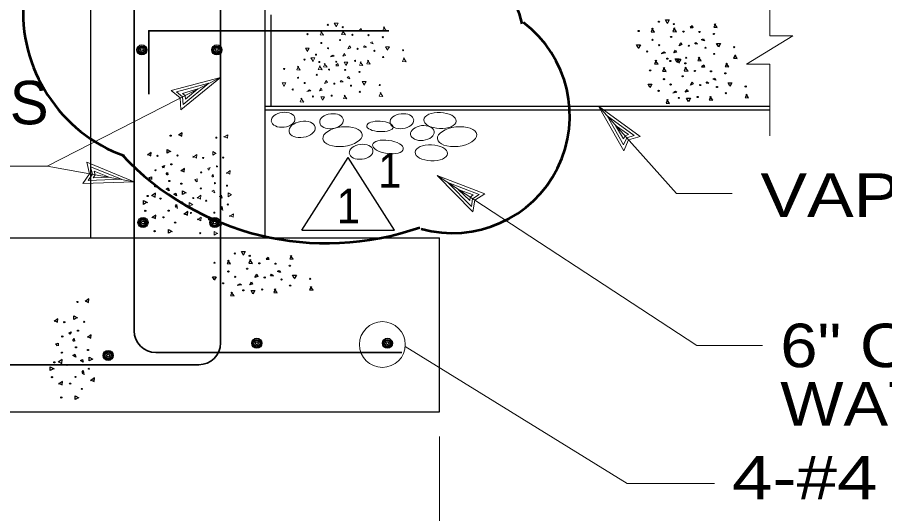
# Model space of a CAD drawing. Extents: x -28.1 to 13.9, y -16.1 to 13.9.
# Drawn here: x -22.908 to -20.417, y 1.852 to 3.278 of the extents above; entities that cross this region are included whole.
import ezdxf
from ezdxf.enums import TextEntityAlignment as Align

# ---------------------------------------------------------------- set-up
doc = ezdxf.new("R2010")
doc.units = 0
doc.header["$LTSCALE"] = 0.05
doc.layers.add('1', color=7, linetype='Continuous', lineweight=13)
doc.layers.add('2', color=7, linetype='Continuous', lineweight=13)

msp = doc.modelspace()

# ---------------------------------------------------------------- linework, layer by layer
at = {"layer": '1', "lineweight": 25}
for p, q in [((-22.19704, 2.64469), (-22.19704, 10.70469)), ((-22.69704, 2.64269), (-22.69704, 10.64469)), ((-22.17904, 3.02269), (-22.17904, 3.28569)), ((-22.19704, 3.02269), (-20.74704, 3.02269)), ((-22.19704, 3.01269), (-20.74704, 3.01269)), ((-22.09105, 2.66671), (-21.95805, 2.87571)), ((-21.82505, 2.66671), (-21.95805, 2.87571)), ((-22.09105, 2.66671), (-21.82505, 2.66671)), ((-23.19604, 2.64469), (-21.69604, 2.64469)), ((-21.69604, 2.14469), (-21.69604, 2.64469)), ((-23.19604, 2.14469), (-21.69604, 2.14469))]:
    msp.add_line(p, q, dxfattribs=at)
at = {"layer": '1', "lineweight": 35}
for p, q in [((-22.57304, 2.37769), (-22.57304, 4.38569)), ((-22.32504, 2.34269), (-22.32504, 4.38569)), ((-22.53082, 3.23983), (-21.84179, 3.23983)), ((-22.51004, 2.31469), (-21.80404, 2.31469)), ((-23.08904, 2.27969), (-22.38704, 2.27969))]:
    msp.add_line(p, q, dxfattribs=at)
at = {"layer": '1'}
for p, q in [((-20.74704, 3.22469), (-20.74704, 3.33369)), ((-20.81404, 3.14369), (-20.68104, 3.22469)), ((-20.74704, 3.22469), (-20.68104, 3.22469)), ((-20.81404, 3.14369), (-20.74704, 3.14369)), ((-20.74704, 2.93769), (-20.74704, 3.14369)), ((-22.32504, 3.10569), (-22.46704, 3.06769)), ((-22.32504, 3.10569), (-22.43904, 3.01269)), ((-22.35804, 3.08869), (-22.45104, 3.06369)), ((-22.39004, 3.07269), (-22.43404, 3.05969)), ((-22.35804, 3.08869), (-22.43204, 3.02769)), ((-22.39004, 3.07269), (-22.42504, 3.04269)), ((-22.43404, 3.04969), (-22.45104, 3.06369)), ((-22.42604, 3.05369), (-22.43404, 3.05969)), ((-22.43204, 3.02769), (-22.43404, 3.04969)), ((-22.42504, 3.04269), (-22.42604, 3.05369)), ((-21.23904, 3.02269), (-21.12004, 2.93569)), ((-21.23904, 3.02269), (-21.16604, 2.89469)), ((-21.21404, 2.99469), (-21.13704, 2.93869)), ((-21.21404, 2.99469), (-21.16704, 2.91169)), ((-21.19004, 2.96769), (-21.16704, 2.92869)), ((-21.19004, 2.96769), (-21.15304, 2.94169)), ((-21.15304, 2.94169), (-21.16304, 2.93769)), ((-21.16304, 2.93769), (-21.16704, 2.92869)), ((-21.15804, 2.93169), (-21.16704, 2.91169)), ((-21.13704, 2.93869), (-21.15804, 2.93169)), ((-22.82304, 2.85069), (-22.57304, 2.80569)), ((-22.57304, 2.80569), (-22.70904, 2.86169)), ((-22.60904, 2.81269), (-22.69804, 2.84869)), ((-22.69304, 2.82769), (-22.69804, 2.84869)), ((-22.70504, 2.80969), (-22.69304, 2.82769)), ((-22.69104, 2.81669), (-22.68504, 2.82569)), ((-22.64504, 2.81869), (-22.69104, 2.81669)), ((-22.64504, 2.81869), (-22.68804, 2.83569)), ((-22.68504, 2.82569), (-22.68804, 2.83569)), ((-21.70304, 2.82369), (-21.56604, 2.77069)), ((-21.70304, 2.82369), (-21.60004, 2.71869)), ((-22.57304, 2.80569), (-22.72004, 2.80069)), ((-22.60904, 2.81269), (-22.70504, 2.80969)), ((-21.67204, 2.80369), (-21.58204, 2.76869)), ((-21.67204, 2.80369), (-21.60404, 2.73469)), ((-21.64204, 2.78369), (-21.60904, 2.75169)), ((-21.64204, 2.78369), (-21.59904, 2.76769)), ((-21.59904, 2.76769), (-21.60804, 2.76169)), ((-21.58204, 2.76869), (-21.60104, 2.75669)), ((-21.60804, 2.76169), (-21.60904, 2.75169)), ((-21.60104, 2.75669), (-21.60404, 2.73469)), ((-21.69604, 2.07369), (-21.69604, 1.48469))]:
    msp.add_line(p, q, dxfattribs=at)
at = {"layer": '1', "lineweight": 35}
msp.add_lwpolyline([(-22.53082, 3.05783), (-22.53082, 3.23983), (-22.51533, 3.23983)], dxfattribs=at)
at = {"layer": '1'}
for points in [[(-22.94304, 2.85069), (-22.82304, 2.85069), (-22.32504, 3.10569)], [(-22.43904, 3.01269), (-22.44104, 3.04669), (-22.46704, 3.06769)], [(-21.23904, 3.02269), (-21.01504, 2.77169), (-20.85504, 2.77169)], [(-21.12004, 2.93569), (-21.15304, 2.92569), (-21.16604, 2.89469)], [(-22.72004, 2.80069), (-22.70104, 2.82869), (-22.70904, 2.86169)], [(-21.70304, 2.82369), (-20.95704, 2.33469), (-20.76804, 2.33469)], [(-21.56604, 2.77069), (-21.59404, 2.75269), (-21.60004, 2.71869)], [(-21.79504, 2.33169), (-21.15704, 1.93869), (-20.90604, 1.93869)]]:
    msp.add_lwpolyline(points, dxfattribs=at)
at = {"layer": '1', "lineweight": 25}
for centre, radius in [((-22.55057, 3.18441), 0.01445), ((-22.55057, 3.18441), 0.01121), ((-22.55057, 3.18441), 0.00822), ((-22.33557, 3.18441), 0.01445), ((-22.33557, 3.18441), 0.01121), ((-22.33557, 3.18441), 0.00822), ((-22.55057, 3.18441), 0.00415), ((-22.33557, 3.18441), 0.00415), ((-22.54757, 2.68841), 0.01445), ((-22.54757, 2.68841), 0.01121), ((-22.54757, 2.68841), 0.00822), ((-22.54757, 2.68841), 0.00415), ((-22.34157, 2.68841), 0.01445), ((-22.34157, 2.68841), 0.01121), ((-22.34157, 2.68841), 0.00822), ((-22.34157, 2.68841), 0.00415), ((-22.22057, 2.34141), 0.01445), ((-22.22057, 2.34141), 0.01121), ((-22.22057, 2.34141), 0.00822), ((-22.22057, 2.34141), 0.00415), ((-21.84557, 2.34141), 0.01445), ((-21.84557, 2.34141), 0.01121), ((-21.84557, 2.34141), 0.00822), ((-21.84557, 2.34141), 0.00415), ((-22.64757, 2.30641), 0.01445), ((-22.64757, 2.30641), 0.01121), ((-22.64757, 2.30641), 0.00822), ((-22.64757, 2.30641), 0.00415)]:
    msp.add_circle(centre, radius, dxfattribs=at)
at = {"layer": '1'}
msp.add_circle((-21.86004, 2.33769), 0.0658, dxfattribs=at)
at = {"layer": '1', "lineweight": 53}
for centre, radius, start, end in [((-21.84293, 3.16628), 0.39543, 13.59077, 148.07844), ((-22.45079, 3.29486), 0.44133, 175.57741, 250.17102), ((-21.65825, 2.99485), 0.3367, 254.38311, 52.80475), ((-22.02007, 3.43532), 0.80646, 223.17013, 289.35765)]:
    msp.add_arc(centre, radius, start, end, dxfattribs=at)
at = {"layer": '1', "lineweight": 35}
for centre, start, end in [((-22.51054, 2.37719), 180, 270), ((-22.38754, 2.34219), 270, 0)]:
    msp.add_arc(centre, 0.0625, start, end, dxfattribs=at)
at = {"layer": '1'}
for centre, major_axis, ratio in [((-22.14504, 2.98369), (0.034, 0.004), 0.623481), ((-22.00604, 2.97969), (0.034, 0.004), 0.623481), ((-21.80404, 2.97969), (0.034, 0.004), 0.623481), ((-21.69454, 2.98169), (0.0465, -0.002), 0.497665), ((-22.09054, 2.95619), (0.0375, 0.0065), 0.610438), ((-21.97454, 2.93519), (0.0565, 0.0065), 0.49427), ((-21.86704, 2.96469), (0.038, -0.002), 0.394455), ((-21.74504, 2.94569), (0.034, 0.004), 0.623481), ((-21.64554, 2.93519), (0.0565, 0.0065), 0.49427), ((-21.92104, 2.89169), (0.034, 0.004), 0.623481), ((-21.84404, 2.90569), (0.044, -0.006), 0.430058), ((-21.71954, 2.88869), (0.0465, -0.002), 0.497665)]:
    msp.add_ellipse(centre, major_axis=major_axis, ratio=ratio, dxfattribs=at)
at = {"layer": '2'}
for p, q in [((-21.92704, 3.24069), (-21.92104, 3.24569)), ((-21.99404, 3.14069), (-21.98804, 3.14569)), ((-22.39404, 2.80569), (-22.39904, 2.81169))]:
    msp.add_line(p, q, dxfattribs=at)
at = {"layer": '2', "lineweight": 25}
for p, q in [((-20.97604, 3.24969), (-20.97004, 3.25469)), ((-20.94304, 3.13669), (-20.93704, 3.14169)), ((-22.52504, 2.81169), (-22.53004, 2.81769)), ((-22.19404, 2.58369), (-22.18804, 2.58869)), ((-22.79304, 2.33369), (-22.79804, 2.33969))]:
    msp.add_line(p, q, dxfattribs=at)
for points in [[(-21.04204, 3.26169), (-21.04704, 3.27069), (-21.03604, 3.27069), (-21.04204, 3.25969)], [(-21.08304, 3.24669), (-21.08804, 3.23669), (-21.07804, 3.23569), (-21.08604, 3.24669)], [(-21.02104, 3.24769), (-21.02604, 3.23769), (-21.01504, 3.23669), (-21.02304, 3.24769)], [(-20.97004, 3.25469), (-20.96804, 3.24769), (-20.97604, 3.24769)], [(-20.90304, 3.25969), (-20.90804, 3.24969), (-20.89804, 3.24869), (-20.90604, 3.25969)], [(-20.94304, 3.21469), (-20.93804, 3.21669), (-20.93504, 3.21069), (-20.94304, 3.21369)], [(-21.12504, 3.19069), (-21.13004, 3.19869), (-21.11904, 3.19869), (-21.12504, 3.18869)], [(-20.96304, 3.20169), (-20.96004, 3.20569), (-20.95504, 3.20169), (-20.96204, 3.20069)], [(-20.89504, 3.19469), (-20.90004, 3.20269), (-20.88904, 3.20269), (-20.89504, 3.19269)], [(-21.05604, 3.17569), (-21.05104, 3.17869), (-21.04704, 3.17569), (-21.05904, 3.17369)], [(-20.84604, 3.17069), (-20.85104, 3.16069), (-20.84104, 3.15969), (-20.84804, 3.17069)], [(-21.07304, 3.15469), (-21.07804, 3.14469), (-21.06804, 3.14369), (-21.07604, 3.15469)], [(-21.01404, 3.14969), (-21.01904, 3.15869), (-21.00804, 3.15869), (-21.01404, 3.14869)], [(-21.00904, 3.14869), (-21.01404, 3.15769), (-21.00304, 3.15769), (-21.00904, 3.14669)], [(-20.94904, 3.16369), (-20.95404, 3.15369), (-20.94404, 3.15269), (-20.95204, 3.16369)], [(-20.93704, 3.14169), (-20.93504, 3.13469), (-20.94304, 3.13469)], [(-20.87004, 3.14669), (-20.87504, 3.13669), (-20.86504, 3.13569), (-20.87304, 3.14669)], [(-21.05004, 3.13369), (-21.05504, 3.12369), (-21.04504, 3.12269), (-21.05304, 3.13369)], [(-20.98804, 3.13469), (-20.99304, 3.12469), (-20.98204, 3.12369), (-20.99004, 3.13469)], [(-20.93004, 3.08869), (-20.92704, 3.09269), (-20.92204, 3.08869), (-20.92904, 3.08769)], [(-20.91004, 3.10169), (-20.90504, 3.10369), (-20.90204, 3.09769), (-20.91004, 3.10069)], [(-20.86204, 3.08169), (-20.86704, 3.08969), (-20.85604, 3.08969), (-20.86204, 3.07969)], [(-21.09204, 3.07769), (-21.09704, 3.08569), (-21.08604, 3.08569), (-21.09204, 3.07569)], [(-21.02304, 3.06269), (-21.01804, 3.06569), (-21.01404, 3.06269), (-21.02604, 3.06069)], [(-21.04004, 3.04169), (-21.04504, 3.03169), (-21.03504, 3.03069), (-21.04304, 3.04169)], [(-20.98104, 3.03669), (-20.98604, 3.04569), (-20.97504, 3.04569), (-20.98104, 3.03569)], [(-20.91604, 3.05069), (-20.92104, 3.04069), (-20.91104, 3.03969), (-20.91904, 3.05069)], [(-20.81304, 3.05769), (-20.81804, 3.04769), (-20.80804, 3.04669), (-20.81504, 3.05769)], [(-22.44604, 2.94169), (-22.43604, 2.93669), (-22.43504, 2.94669), (-22.44604, 2.93969)], [(-22.47004, 2.89269), (-22.47804, 2.88769), (-22.47804, 2.89869), (-22.46804, 2.89269)], [(-22.53504, 2.88469), (-22.52504, 2.87969), (-22.52404, 2.88969), (-22.53504, 2.88169)], [(-22.49004, 2.84469), (-22.49204, 2.84969), (-22.48604, 2.85269), (-22.48904, 2.84469)], [(-22.43904, 2.83869), (-22.42904, 2.83369), (-22.42804, 2.84369), (-22.43904, 2.83569)], [(-22.53004, 2.81769), (-22.52304, 2.81969), (-22.52304, 2.81169)], [(-22.47704, 2.82469), (-22.48104, 2.82769), (-22.47704, 2.83269), (-22.47604, 2.82569)], [(-22.52304, 2.76669), (-22.51304, 2.76169), (-22.51204, 2.77269), (-22.52304, 2.76469)], [(-22.42504, 2.77369), (-22.43404, 2.76869), (-22.43404, 2.77969), (-22.42404, 2.77369)], [(-22.53704, 2.74569), (-22.54604, 2.74069), (-22.54604, 2.75169), (-22.53504, 2.74569)], [(-22.45104, 2.73169), (-22.45404, 2.73669), (-22.45104, 2.74069), (-22.44904, 2.72869)], [(-22.43004, 2.71469), (-22.42004, 2.70969), (-22.41904, 2.71969), (-22.43004, 2.71169)], [(-22.52204, 2.70469), (-22.51204, 2.69969), (-22.51104, 2.70969), (-22.52204, 2.70169)], [(-22.46604, 2.66269), (-22.47404, 2.65769), (-22.47404, 2.66869), (-22.46404, 2.66269)], [(-22.26004, 2.59569), (-22.26504, 2.60469), (-22.25404, 2.60469), (-22.26004, 2.59369)], [(-22.12104, 2.59369), (-22.12604, 2.58369), (-22.11604, 2.58269), (-22.12404, 2.59369)], [(-22.30104, 2.58069), (-22.30604, 2.57069), (-22.29604, 2.56969), (-22.30404, 2.58069)], [(-22.23904, 2.58169), (-22.24404, 2.57169), (-22.23304, 2.57069), (-22.24104, 2.58169)], [(-22.18804, 2.58869), (-22.18604, 2.58169), (-22.19404, 2.58169)], [(-22.16104, 2.54869), (-22.15604, 2.55069), (-22.15304, 2.54469), (-22.16104, 2.54769)], [(-22.34304, 2.52469), (-22.34804, 2.53269), (-22.33704, 2.53269), (-22.34304, 2.52269)], [(-22.18104, 2.53569), (-22.17804, 2.53969), (-22.17304, 2.53569), (-22.18004, 2.53469)], [(-22.11304, 2.52869), (-22.11804, 2.53669), (-22.10704, 2.53669), (-22.11304, 2.52669)], [(-22.27404, 2.50969), (-22.26904, 2.51269), (-22.26504, 2.50969), (-22.27704, 2.50769)], [(-22.23204, 2.48369), (-22.23704, 2.49269), (-22.22604, 2.49269), (-22.23204, 2.48269)], [(-22.16704, 2.49769), (-22.17204, 2.48769), (-22.16204, 2.48669), (-22.17004, 2.49769)], [(-22.06404, 2.50469), (-22.06904, 2.49469), (-22.05904, 2.49369), (-22.06604, 2.50469)], [(-22.71404, 2.46369), (-22.70404, 2.45869), (-22.70304, 2.46869), (-22.71404, 2.46169)], [(-22.29104, 2.48869), (-22.29604, 2.47869), (-22.28604, 2.47769), (-22.29404, 2.48869)], [(-22.73804, 2.41469), (-22.74604, 2.40969), (-22.74604, 2.42069), (-22.73604, 2.41469)], [(-22.80304, 2.40669), (-22.79304, 2.40169), (-22.79204, 2.41169), (-22.80304, 2.40369)], [(-22.75804, 2.36669), (-22.76004, 2.37169), (-22.75404, 2.37469), (-22.75704, 2.36669)], [(-22.79804, 2.33969), (-22.79104, 2.34169), (-22.79104, 2.33369)], [(-22.74504, 2.34669), (-22.74904, 2.34969), (-22.74504, 2.35469), (-22.74404, 2.34769)], [(-22.70704, 2.36069), (-22.69704, 2.35569), (-22.69604, 2.36569), (-22.70704, 2.35769)], [(-22.79104, 2.28869), (-22.78104, 2.28369), (-22.78004, 2.29469), (-22.79104, 2.28669)], [(-22.69304, 2.29569), (-22.70204, 2.29069), (-22.70204, 2.30169), (-22.69204, 2.29569)], [(-22.80504, 2.26769), (-22.81404, 2.26269), (-22.81404, 2.27369), (-22.80304, 2.26769)], [(-22.71904, 2.25369), (-22.72204, 2.25869), (-22.71904, 2.26269), (-22.71704, 2.25069)], [(-22.79004, 2.22669), (-22.78004, 2.22169), (-22.77904, 2.23169), (-22.79004, 2.22369)], [(-22.69804, 2.23669), (-22.68804, 2.23169), (-22.68704, 2.24169), (-22.69804, 2.23369)], [(-22.73404, 2.18469), (-22.74204, 2.17969), (-22.74204, 2.19069), (-22.73204, 2.18469)]]:
    msp.add_lwpolyline(points, dxfattribs=at)
at = {"layer": '2'}
for points in [[(-21.99304, 3.25269), (-21.99804, 3.26169), (-21.98704, 3.26169), (-21.99304, 3.25069)], [(-21.97204, 3.23869), (-21.97704, 3.22869), (-21.96604, 3.22769), (-21.97404, 3.23869)], [(-21.92104, 3.24569), (-21.91904, 3.23869), (-21.92704, 3.23869)], [(-21.85404, 3.25069), (-21.85904, 3.24069), (-21.84904, 3.23969), (-21.85704, 3.25069)], [(-22.03404, 3.23769), (-22.03904, 3.22769), (-22.02904, 3.22669), (-22.03704, 3.23769)], [(-22.07604, 3.18169), (-22.08104, 3.18969), (-22.07004, 3.18969), (-22.07604, 3.17969)], [(-21.91404, 3.19269), (-21.91104, 3.19669), (-21.90604, 3.19269), (-21.91304, 3.19169)], [(-21.89404, 3.20569), (-21.88904, 3.20769), (-21.88604, 3.20169), (-21.89404, 3.20469)], [(-21.84604, 3.18569), (-21.85104, 3.19369), (-21.84004, 3.19369), (-21.84604, 3.18369)], [(-22.00704, 3.16669), (-22.00204, 3.16969), (-21.99804, 3.16669), (-22.01004, 3.16469)], [(-22.06004, 3.15269), (-22.06504, 3.16169), (-22.05404, 3.16169), (-22.06004, 3.15069)], [(-22.02404, 3.14569), (-22.02904, 3.13569), (-22.01904, 3.13469), (-22.02704, 3.14569)], [(-21.98804, 3.14569), (-21.98604, 3.13869), (-21.99404, 3.13869)], [(-21.96504, 3.14069), (-21.97004, 3.14969), (-21.95904, 3.14969), (-21.96504, 3.13969)], [(-21.92104, 3.15069), (-21.92604, 3.14069), (-21.91604, 3.13969), (-21.92404, 3.15069)], [(-21.90004, 3.15469), (-21.90504, 3.14469), (-21.89504, 3.14369), (-21.90304, 3.15469)], [(-21.79704, 3.16169), (-21.80204, 3.15169), (-21.79204, 3.15069), (-21.79904, 3.16169)], [(-22.10104, 3.13769), (-22.10604, 3.12769), (-22.09604, 3.12669), (-22.10404, 3.13769)], [(-22.03904, 3.13869), (-22.04404, 3.12869), (-22.03304, 3.12769), (-22.04104, 3.13869)], [(-22.14304, 3.08169), (-22.14804, 3.08969), (-22.13704, 3.08969), (-22.14304, 3.07969)], [(-21.98104, 3.09269), (-21.97804, 3.09669), (-21.97304, 3.09269), (-21.98004, 3.09169)], [(-21.96104, 3.10569), (-21.95604, 3.10769), (-21.95304, 3.10169), (-21.96104, 3.10469)], [(-21.91304, 3.08569), (-21.91804, 3.09369), (-21.90704, 3.09369), (-21.91304, 3.08369)], [(-22.07404, 3.06669), (-22.06904, 3.06969), (-22.06504, 3.06669), (-22.07704, 3.06469)], [(-22.09104, 3.04569), (-22.09604, 3.03569), (-22.08604, 3.03469), (-22.09404, 3.04569)], [(-22.03204, 3.04069), (-22.03704, 3.04969), (-22.02604, 3.04969), (-22.03204, 3.03969)], [(-21.96704, 3.05469), (-21.97204, 3.04469), (-21.96204, 3.04369), (-21.97004, 3.05469)], [(-21.86404, 3.06169), (-21.86904, 3.05169), (-21.85904, 3.05069), (-21.86604, 3.06169)], [(-22.31504, 2.93569), (-22.30504, 2.93069), (-22.30404, 2.94069), (-22.31504, 2.93369)], [(-22.33904, 2.88669), (-22.34704, 2.88169), (-22.34704, 2.89269), (-22.33704, 2.88669)], [(-22.40404, 2.87869), (-22.39404, 2.87369), (-22.39304, 2.88369), (-22.40404, 2.87569)], [(-22.35904, 2.83869), (-22.36104, 2.84369), (-22.35504, 2.84669), (-22.35804, 2.83869)], [(-22.34604, 2.81869), (-22.35004, 2.82169), (-22.34604, 2.82669), (-22.34504, 2.81969)], [(-22.30804, 2.83269), (-22.29804, 2.82769), (-22.29704, 2.83769), (-22.30804, 2.82969)], [(-22.39904, 2.81169), (-22.39204, 2.81369), (-22.39204, 2.80569)], [(-22.39204, 2.76069), (-22.38204, 2.75569), (-22.38104, 2.76669), (-22.39204, 2.75869)], [(-22.29404, 2.76769), (-22.30304, 2.76269), (-22.30304, 2.77369), (-22.29304, 2.76769)], [(-22.40604, 2.73969), (-22.41504, 2.73469), (-22.41504, 2.74569), (-22.40404, 2.73969)], [(-22.32004, 2.72569), (-22.32304, 2.73069), (-22.32004, 2.73469), (-22.31804, 2.72269)], [(-22.39104, 2.69869), (-22.38104, 2.69369), (-22.38004, 2.70369), (-22.39104, 2.69569)], [(-22.29904, 2.70869), (-22.28904, 2.70369), (-22.28804, 2.71369), (-22.29904, 2.70569)], [(-22.33504, 2.65669), (-22.34304, 2.65169), (-22.34304, 2.66269), (-22.33304, 2.65669)]]:
    msp.add_lwpolyline(points, dxfattribs=at)
for points in [[(-21.95904, 3.18769), (-21.95404, 3.19669), (-21.95104, 3.19069)], [(-21.97404, 3.16669), (-21.96904, 3.17469), (-21.96604, 3.16869)], [(-22.02604, 3.08769), (-22.02104, 3.09669), (-22.01804, 3.09069)], [(-22.04104, 3.06669), (-22.03604, 3.07469), (-22.03304, 3.06869)], [(-22.34104, 2.77369), (-22.35004, 2.77869), (-22.34404, 2.78169)], [(-22.32004, 2.75869), (-22.32804, 2.76369), (-22.32204, 2.76669)]]:
    msp.add_lwpolyline(points, close=True, dxfattribs=at)
at = {"layer": '2', "lineweight": 25}
for points in [[(-21.00804, 3.19669), (-21.00304, 3.20569), (-21.00004, 3.19969)], [(-21.02304, 3.17569), (-21.01804, 3.18369), (-21.01504, 3.17769)], [(-20.97504, 3.08369), (-20.97004, 3.09269), (-20.96704, 3.08669)], [(-20.99004, 3.06269), (-20.98504, 3.07069), (-20.98204, 3.06469)], [(-22.47204, 2.77969), (-22.48104, 2.78469), (-22.47504, 2.78769)], [(-22.45104, 2.76469), (-22.45904, 2.76969), (-22.45304, 2.77269)], [(-22.24104, 2.50969), (-22.23604, 2.51769), (-22.23304, 2.51169)], [(-22.22604, 2.53069), (-22.22104, 2.53969), (-22.21804, 2.53369)], [(-22.74004, 2.30169), (-22.74904, 2.30669), (-22.74304, 2.30969)], [(-22.71904, 2.28669), (-22.72704, 2.29169), (-22.72104, 2.29469)]]:
    msp.add_lwpolyline(points, close=True, dxfattribs=at)
for centre in [(-21.06579, 3.26556), (-21.12404, 3.23881), (-21.02304, 3.25881), (-20.99529, 3.23706), (-21.08429, 3.21356), (-21.03054, 3.22181), (-20.94904, 3.23606), (-20.90779, 3.23031), (-21.06504, 3.19831), (-20.98004, 3.19656), (-20.93204, 3.19081), (-20.84954, 3.19256), (-21.09954, 3.17981), (-20.90679, 3.17306), (-21.04154, 3.15956), (-21.03279, 3.15256), (-20.99004, 3.14581), (-20.98754, 3.16206), (-21.09104, 3.12581), (-20.96229, 3.12406), (-20.91604, 3.12306), (-20.87479, 3.11731), (-21.05129, 3.10056), (-20.99754, 3.10881), (-21.06654, 3.06681), (-21.03204, 3.08531), (-20.94704, 3.08356), (-20.89904, 3.07781), (-20.81654, 3.07956), (-21.00854, 3.04656), (-20.95454, 3.04906), (-20.87379, 3.06006), (-22.46792, 2.93819), (-22.50567, 2.87994), (-22.44842, 2.88094), (-22.51142, 2.83869), (-22.46617, 2.85569), (-22.51242, 2.79244), (-22.47192, 2.80769), (-22.43742, 2.80019), (-22.53417, 2.76469), (-22.49717, 2.75719), (-22.43492, 2.74619), (-22.54092, 2.72194), (-22.47367, 2.72269), (-22.48892, 2.70344), (-22.45517, 2.68819), (-22.51417, 2.66369), (-22.28379, 2.59956), (-22.24104, 2.59281), (-22.34204, 2.57281), (-22.21329, 2.57106), (-22.16704, 2.57006), (-22.12579, 2.56431), (-22.30229, 2.54756), (-22.24854, 2.55581), (-22.28304, 2.53231), (-22.19804, 2.53056), (-22.15004, 2.52481), (-22.06754, 2.52656), (-22.31754, 2.51381), (-22.25954, 2.49356), (-22.20554, 2.49606), (-22.12479, 2.50706), (-22.73592, 2.46019), (-22.77367, 2.40194), (-22.71642, 2.40294), (-22.73417, 2.37769), (-22.77942, 2.36069), (-22.73992, 2.32969), (-22.70542, 2.32219), (-22.78042, 2.31444), (-22.80217, 2.28669), (-22.76517, 2.27919), (-22.70292, 2.26819), (-22.80892, 2.24394), (-22.74167, 2.24469), (-22.75692, 2.22544), (-22.72317, 2.21019), (-22.78217, 2.18569)]:
    msp.add_circle(centre, 0.00162, dxfattribs=at)
at = {"layer": '2'}
for centre in [(-22.01679, 3.25656), (-21.97404, 3.24981), (-22.07504, 3.22981), (-21.98154, 3.21281), (-21.94629, 3.22806), (-21.90004, 3.22706), (-21.85879, 3.22131), (-22.03529, 3.20456), (-22.01604, 3.18931), (-21.93104, 3.18756), (-22.05054, 3.17081), (-21.88304, 3.18181), (-21.85779, 3.16406), (-21.80054, 3.18356), (-22.08379, 3.15656), (-22.04104, 3.14981), (-21.99254, 3.15056), (-21.93854, 3.15306), (-22.14204, 3.12981), (-22.04854, 3.11281), (-22.01329, 3.12806), (-21.96704, 3.12706), (-21.92579, 3.12131), (-22.10229, 3.10456), (-22.08304, 3.08931), (-21.99804, 3.08756), (-22.11754, 3.07081), (-21.95004, 3.08181), (-21.92479, 3.06406), (-21.86754, 3.08356), (-22.05954, 3.05056), (-22.00554, 3.05306), (-22.33692, 2.93219), (-22.37467, 2.87394), (-22.31742, 2.87494), (-22.33517, 2.84969), (-22.38042, 2.83269), (-22.34092, 2.80169), (-22.30642, 2.79419), (-22.38142, 2.78644), (-22.40317, 2.75869), (-22.36617, 2.75119), (-22.30392, 2.74019), (-22.40992, 2.71594), (-22.34267, 2.71669), (-22.35792, 2.69744), (-22.32417, 2.68219), (-22.38317, 2.65769)]:
    msp.add_circle(centre, 0.00162, dxfattribs=at)

# ---------------------------------------------------------------- texts
at = {"layer": '1'}
msp.add_text('DOWELS', height=0.125, dxfattribs=at).set_placement((-23.18098, 2.97069), align=Align.CENTER)
at = {"layer": '1', "width": 0.9}
for p in [(-21.83872, 2.78871), (-21.95772, 2.68571)]:
    msp.add_text('1', height=0.1, dxfattribs=at).set_placement(p, align=Align.CENTER)
at = {"layer": '1'}
for s, width, p in [('VAPOR BARRIER (TYP.)', 1.2, (-20.77404, 2.70469)), ('6" CAPILLARY', 1.15, (-20.71704, 2.27269)), ('WATER BARRIER (TYP.)', 1.15, (-20.71704, 2.10469)), ('4-#4', 1.25, (-20.85604, 1.89269))]:
    msp.add_text(s, height=0.125, dxfattribs=dict(at, width=width)).set_placement(p)

doc.saveas('drawing.dxf')
